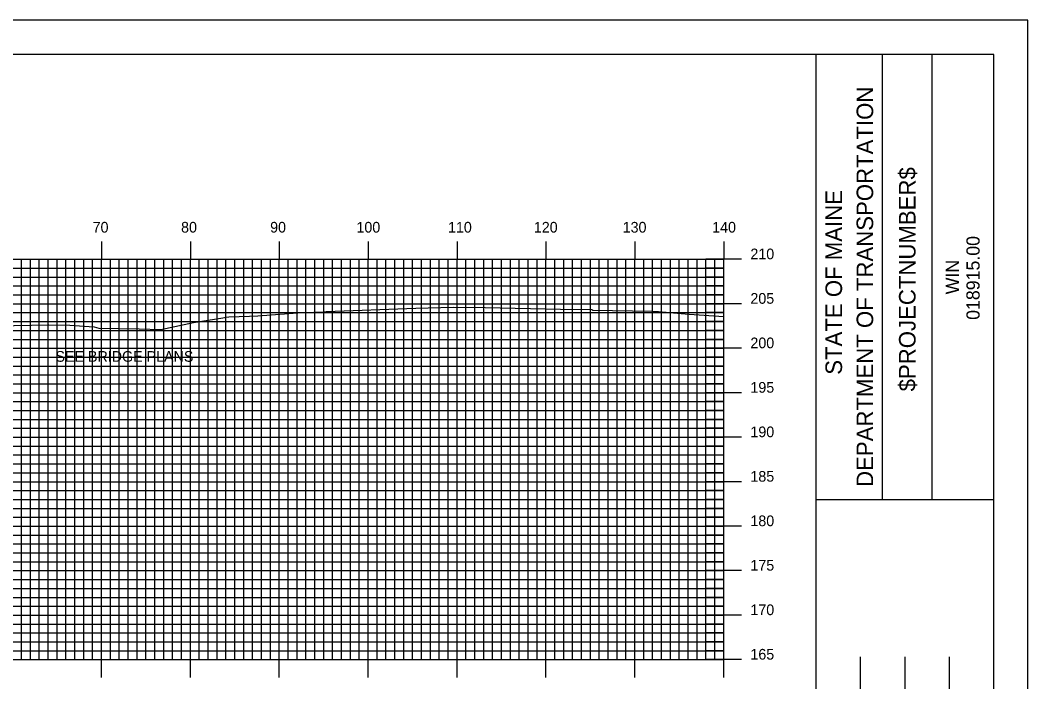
# Model space of a CAD drawing. Extents: x 1795633 to 1795976, y 442591 to 442811.
# Drawn here: x 1795859.7 to 1795973.1, y 442736.2 to 442810.5 of the extents above; entities that cross this region are included whole.
import ezdxf

# ---------------------------------------------------------------- set-up
doc = ezdxf.new("R2010")
doc.units = 0
for name, color, linetype in [('ANNOTATION', 7, 'Continuous'), ('BORDER', 7, 'Continuous'), ('H_V ANNOTATION', 7, 'Continuous'), ('MAJOR', 7, 'Continuous'), ('MINOR', 7, 'Continuous'), ('PLOT BOUNDARY', 7, 'Continuous'), ('S_Roadway_Centerline', 7, 'Continuous')]:
    doc.layers.add(name, color=color, linetype=linetype)

msp = doc.modelspace()

# ---------------------------------------------------------------- linework, layer by layer
at = {"layer": 'BORDER'}
for p, q in [((1795949.28, 442596.67), (1795949.28, 442806.67)), ((1795956.74, 442756.66), (1795956.74, 442806.66)), ((1795962.33, 442756.66), (1795962.33, 442806.66)), ((1795949.28, 442756.65), (1795969.28, 442756.65)), ((1795954.28, 442721.67), (1795954.28, 442738.97)), ((1795959.28, 442721.67), (1795959.28, 442738.97)), ((1795964.28, 442721.67), (1795964.28, 442738.97))]:
    msp.add_line(p, q, dxfattribs=at)
msp.add_lwpolyline([(1795649.28, 442596.67), (1795969.28, 442596.67), (1795969.28, 442806.67), (1795649.28, 442806.67)], close=True, dxfattribs=at)
at = {"layer": 'MAJOR'}
for p, q in [((1795868.88, 442785.67), (1795868.88, 442783.67)), ((1795878.88, 442785.67), (1795878.88, 442783.67)), ((1795888.88, 442785.67), (1795888.88, 442783.67)), ((1795898.88, 442785.67), (1795898.88, 442783.67)), ((1795908.88, 442785.67), (1795908.88, 442783.67)), ((1795918.88, 442785.67), (1795918.88, 442783.67)), ((1795928.88, 442785.67), (1795928.88, 442783.67)), ((1795938.88, 442785.67), (1795938.88, 442783.67)), ((1795658.88, 442783.67), (1795938.88, 442783.67)), ((1795658.88, 442783.67), (1795938.88, 442783.67)), ((1795868.88, 442738.67), (1795868.88, 442783.67)), ((1795878.88, 442738.67), (1795878.88, 442783.67)), ((1795888.88, 442738.67), (1795888.88, 442783.67)), ((1795898.88, 442738.67), (1795898.88, 442783.67)), ((1795908.88, 442738.67), (1795908.88, 442783.67)), ((1795918.88, 442738.67), (1795918.88, 442783.67)), ((1795928.88, 442738.67), (1795928.88, 442783.67)), ((1795940.88, 442783.67), (1795936.88, 442783.67)), ((1795938.88, 442738.67), (1795938.88, 442783.67)), ((1795938.88, 442738.67), (1795938.88, 442783.67)), ((1795658.88, 442778.67), (1795938.88, 442778.67)), ((1795940.88, 442778.67), (1795936.88, 442778.67)), ((1795658.88, 442773.67), (1795938.88, 442773.67)), ((1795940.88, 442773.67), (1795936.88, 442773.67)), ((1795658.88, 442768.67), (1795938.88, 442768.67)), ((1795940.88, 442768.67), (1795936.88, 442768.67)), ((1795658.88, 442763.67), (1795938.88, 442763.67)), ((1795940.88, 442763.67), (1795936.88, 442763.67)), ((1795658.88, 442758.67), (1795938.88, 442758.67)), ((1795940.88, 442758.67), (1795936.88, 442758.67)), ((1795658.88, 442753.67), (1795938.88, 442753.67)), ((1795940.88, 442753.67), (1795936.88, 442753.67)), ((1795658.88, 442748.67), (1795938.88, 442748.67)), ((1795940.88, 442748.67), (1795936.88, 442748.67)), ((1795658.88, 442743.67), (1795938.88, 442743.67)), ((1795940.88, 442743.67), (1795936.88, 442743.67)), ((1795658.88, 442738.67), (1795938.88, 442738.67)), ((1795658.88, 442738.67), (1795938.88, 442738.67)), ((1795868.88, 442736.66), (1795868.88, 442738.67)), ((1795878.88, 442736.66), (1795878.88, 442738.67)), ((1795888.88, 442736.66), (1795888.88, 442738.67)), ((1795898.88, 442736.66), (1795898.88, 442738.67)), ((1795908.88, 442736.66), (1795908.88, 442738.67)), ((1795918.88, 442736.66), (1795918.88, 442738.67)), ((1795928.88, 442736.66), (1795928.88, 442738.67)), ((1795940.88, 442738.67), (1795936.88, 442738.67)), ((1795938.88, 442736.66), (1795938.88, 442738.67))]:
    msp.add_line(p, q, dxfattribs=at)
at = {"layer": 'MINOR'}
for p, q in [((1795859.88, 442738.67), (1795859.88, 442783.67)), ((1795860.88, 442738.67), (1795860.88, 442783.67)), ((1795861.88, 442738.67), (1795861.88, 442783.67)), ((1795862.88, 442738.67), (1795862.88, 442783.67)), ((1795863.88, 442738.67), (1795863.88, 442783.67)), ((1795864.88, 442738.67), (1795864.88, 442783.67)), ((1795865.88, 442738.67), (1795865.88, 442783.67)), ((1795866.88, 442738.67), (1795866.88, 442783.67)), ((1795867.88, 442738.67), (1795867.88, 442783.67)), ((1795869.88, 442738.67), (1795869.88, 442783.67)), ((1795870.88, 442738.67), (1795870.88, 442783.67)), ((1795871.88, 442738.67), (1795871.88, 442783.67)), ((1795872.88, 442738.67), (1795872.88, 442783.67)), ((1795873.88, 442738.67), (1795873.88, 442783.67)), ((1795874.88, 442738.67), (1795874.88, 442783.67)), ((1795875.88, 442738.67), (1795875.88, 442783.67)), ((1795876.88, 442738.67), (1795876.88, 442783.67)), ((1795877.88, 442738.67), (1795877.88, 442783.67)), ((1795879.88, 442738.67), (1795879.88, 442783.67)), ((1795880.88, 442738.67), (1795880.88, 442783.67)), ((1795881.88, 442738.67), (1795881.88, 442783.67)), ((1795882.88, 442738.67), (1795882.88, 442783.67)), ((1795883.88, 442738.67), (1795883.88, 442783.67)), ((1795884.88, 442738.67), (1795884.88, 442783.67)), ((1795885.88, 442738.67), (1795885.88, 442783.67)), ((1795886.88, 442738.67), (1795886.88, 442783.67)), ((1795887.88, 442738.67), (1795887.88, 442783.67)), ((1795889.88, 442738.67), (1795889.88, 442783.67)), ((1795890.88, 442738.67), (1795890.88, 442783.67)), ((1795891.88, 442738.67), (1795891.88, 442783.67)), ((1795892.88, 442738.67), (1795892.88, 442783.67)), ((1795893.88, 442738.67), (1795893.88, 442783.67)), ((1795894.88, 442738.67), (1795894.88, 442783.67)), ((1795895.88, 442738.67), (1795895.88, 442783.67)), ((1795896.88, 442738.67), (1795896.88, 442783.67)), ((1795897.88, 442738.67), (1795897.88, 442783.67)), ((1795899.88, 442738.67), (1795899.88, 442783.67)), ((1795900.88, 442738.67), (1795900.88, 442783.67)), ((1795901.88, 442738.67), (1795901.88, 442783.67)), ((1795902.88, 442738.67), (1795902.88, 442783.67)), ((1795903.88, 442738.67), (1795903.88, 442783.67)), ((1795904.88, 442738.67), (1795904.88, 442783.67)), ((1795905.88, 442738.67), (1795905.88, 442783.67)), ((1795906.88, 442738.67), (1795906.88, 442783.67)), ((1795907.88, 442738.67), (1795907.88, 442783.67)), ((1795909.88, 442738.67), (1795909.88, 442783.67)), ((1795910.88, 442738.67), (1795910.88, 442783.67)), ((1795911.88, 442738.67), (1795911.88, 442783.67)), ((1795912.88, 442738.67), (1795912.88, 442783.67)), ((1795913.88, 442738.67), (1795913.88, 442783.67)), ((1795914.88, 442738.67), (1795914.88, 442783.67)), ((1795915.88, 442738.67), (1795915.88, 442783.67)), ((1795916.88, 442738.67), (1795916.88, 442783.67)), ((1795917.88, 442738.67), (1795917.88, 442783.67)), ((1795919.88, 442738.67), (1795919.88, 442783.67)), ((1795920.88, 442738.67), (1795920.88, 442783.67)), ((1795921.88, 442738.67), (1795921.88, 442783.67)), ((1795922.88, 442738.67), (1795922.88, 442783.67)), ((1795923.88, 442738.67), (1795923.88, 442783.67)), ((1795924.88, 442738.67), (1795924.88, 442783.67)), ((1795925.88, 442738.67), (1795925.88, 442783.67)), ((1795926.88, 442738.67), (1795926.88, 442783.67)), ((1795927.88, 442738.67), (1795927.88, 442783.67)), ((1795929.88, 442738.67), (1795929.88, 442783.67)), ((1795930.88, 442738.67), (1795930.88, 442783.67)), ((1795931.88, 442738.67), (1795931.88, 442783.67)), ((1795932.88, 442738.67), (1795932.88, 442783.67)), ((1795933.88, 442738.67), (1795933.88, 442783.67)), ((1795934.88, 442738.67), (1795934.88, 442783.67)), ((1795935.88, 442738.67), (1795935.88, 442783.67)), ((1795936.88, 442738.67), (1795936.88, 442783.67)), ((1795937.88, 442738.67), (1795937.88, 442783.67)), ((1795658.88, 442782.67), (1795938.88, 442782.67)), ((1795938.88, 442782.67), (1795936.88, 442782.67)), ((1795658.88, 442781.67), (1795938.88, 442781.67)), ((1795658.88, 442780.67), (1795938.88, 442780.67)), ((1795938.88, 442781.67), (1795936.88, 442781.67)), ((1795938.88, 442780.67), (1795936.88, 442780.67)), ((1795658.88, 442779.67), (1795938.88, 442779.67)), ((1795938.88, 442779.67), (1795936.88, 442779.67)), ((1795658.88, 442777.67), (1795938.88, 442777.67)), ((1795938.88, 442777.67), (1795936.88, 442777.67)), ((1795658.88, 442776.67), (1795938.88, 442776.67)), ((1795938.88, 442776.67), (1795936.88, 442776.67)), ((1795658.88, 442775.67), (1795938.88, 442775.67)), ((1795938.88, 442775.67), (1795936.88, 442775.67)), ((1795658.88, 442774.67), (1795938.88, 442774.67)), ((1795938.88, 442774.67), (1795936.88, 442774.67)), ((1795658.88, 442772.67), (1795938.88, 442772.67)), ((1795938.88, 442772.67), (1795936.88, 442772.67)), ((1795658.88, 442771.67), (1795938.88, 442771.67)), ((1795938.88, 442771.67), (1795936.88, 442771.67)), ((1795658.88, 442770.67), (1795938.88, 442770.67)), ((1795938.88, 442770.67), (1795936.88, 442770.67)), ((1795658.88, 442769.67), (1795938.88, 442769.67)), ((1795938.88, 442769.67), (1795936.88, 442769.67)), ((1795658.88, 442767.67), (1795938.88, 442767.67)), ((1795938.88, 442767.67), (1795936.88, 442767.67)), ((1795658.88, 442766.67), (1795938.88, 442766.67)), ((1795938.88, 442766.67), (1795936.88, 442766.67)), ((1795658.88, 442765.67), (1795938.88, 442765.67)), ((1795938.88, 442765.67), (1795936.88, 442765.67)), ((1795658.88, 442764.67), (1795938.88, 442764.67)), ((1795938.88, 442764.67), (1795936.88, 442764.67)), ((1795658.88, 442762.67), (1795938.88, 442762.67)), ((1795938.88, 442762.67), (1795936.88, 442762.67)), ((1795658.88, 442761.67), (1795938.88, 442761.67)), ((1795658.88, 442760.67), (1795938.88, 442760.67)), ((1795938.88, 442760.67), (1795936.88, 442760.67)), ((1795658.88, 442759.67), (1795938.88, 442759.67)), ((1795938.88, 442759.67), (1795936.88, 442759.67)), ((1795658.88, 442757.67), (1795938.88, 442757.67)), ((1795938.88, 442757.67), (1795936.88, 442757.67)), ((1795658.88, 442756.67), (1795938.88, 442756.67)), ((1795658.88, 442755.67), (1795938.88, 442755.67)), ((1795938.88, 442756.67), (1795936.88, 442756.67)), ((1795938.88, 442755.67), (1795936.88, 442755.67)), ((1795658.88, 442754.67), (1795938.88, 442754.67)), ((1795938.88, 442754.67), (1795936.88, 442754.67)), ((1795834.58, 442752.67), (1795938.88, 442752.67)), ((1795938.88, 442752.67), (1795936.88, 442752.67)), ((1795658.88, 442751.67), (1795938.88, 442751.67)), ((1795938.88, 442751.67), (1795936.88, 442751.67)), ((1795658.88, 442750.67), (1795938.88, 442750.67)), ((1795938.88, 442750.67), (1795936.88, 442750.67)), ((1795658.88, 442749.67), (1795938.88, 442749.67)), ((1795938.88, 442749.67), (1795936.88, 442749.67)), ((1795658.88, 442747.67), (1795938.88, 442747.67)), ((1795658.88, 442746.67), (1795938.88, 442746.67)), ((1795938.88, 442747.67), (1795936.88, 442747.67)), ((1795938.88, 442746.67), (1795936.88, 442746.67)), ((1795658.88, 442745.67), (1795938.88, 442745.67)), ((1795938.88, 442745.67), (1795936.88, 442745.67)), ((1795658.88, 442744.67), (1795938.88, 442744.67)), ((1795938.88, 442744.67), (1795936.88, 442744.67)), ((1795658.88, 442742.67), (1795938.88, 442742.67)), ((1795938.88, 442742.67), (1795936.88, 442742.67)), ((1795658.88, 442741.67), (1795938.88, 442741.67)), ((1795938.88, 442741.67), (1795936.88, 442741.67)), ((1795658.88, 442740.67), (1795938.88, 442740.67)), ((1795938.88, 442740.67), (1795936.88, 442740.67)), ((1795658.88, 442739.67), (1795938.88, 442739.67)), ((1795938.88, 442739.67), (1795936.88, 442739.67))]:
    msp.add_line(p, q, dxfattribs=at)
at = {"layer": 'PLOT BOUNDARY'}
msp.add_lwpolyline([(1795633.09, 442590.55), (1795973.09, 442590.55), (1795973.09, 442810.55), (1795633.09, 442810.55)], close=True, dxfattribs=at)
at = {"layer": 'S_Roadway_Centerline'}
msp.add_lwpolyline([(1795857.06, 442776.18), (1795862.97, 442776.3), (1795865.3, 442776.25), (1795868.04, 442776.08), (1795868.56, 442775.91), (1795873.13, 442775.85), (1795875.56, 442775.78), (1795875.57, 442775.77), (1795879.24, 442776.55), (1795882.51, 442777.1), (1795882.9, 442777.18), (1795883.22, 442777.19), (1795885.53, 442777.29), (1795886.45, 442777.33), (1795891.44, 442777.68), (1795891.67, 442777.7), (1795893.86, 442777.78), (1795894.14, 442777.79), (1795904.23, 442778.16), (1795908.44, 442778.29), (1795912.03, 442778.24), (1795920.52, 442778.08), (1795924.05, 442778.03), (1795924.15, 442777.94), (1795930.83, 442777.82), (1795931.53, 442777.79), (1795934.09, 442777.58), (1795934.99, 442777.5), (1795938.88, 442777.25)], dxfattribs=at)

# ---------------------------------------------------------------- texts
at = {"layer": 'ANNOTATION'}
msp.add_text('SEE BRIDGE PLANS', height=1.2, dxfattribs=at).set_placement((1795863.7, 442772.15))
at = {"layer": 'BORDER'}
for s, height, p in [('DEPARTMENT OF TRANSPORTATION', 1.8635, (1795955.69, 442758.08)), ('$PROJECTNUMBER$', 1.8635, (1795960.46, 442768.82)), ('STATE OF MAINE', 1.8635, (1795952.19, 442770.69)), ('018915.00', 1.491, (1795967.67, 442776.86)), ('WIN', 1.491, (1795965.35, 442779.73))]:
    msp.add_text(s, height=height, rotation=90, dxfattribs=at).set_placement(p)
at = {"layer": 'H_V ANNOTATION'}
for s, p in [('70', (1795867.88, 442786.67)), ('80', (1795877.83, 442786.67)), ('90', (1795887.85, 442786.67)), ('100', (1795897.56, 442786.67)), ('110', (1795907.86, 442786.67)), ('120', (1795917.52, 442786.67)), ('130', (1795927.51, 442786.67)), ('140', (1795937.58, 442786.67)), ('210', (1795941.88, 442783.67)), ('205', (1795941.88, 442778.67)), ('200', (1795941.88, 442773.67)), ('195', (1795941.88, 442768.67)), ('190', (1795941.88, 442763.67)), ('185', (1795941.88, 442758.67)), ('180', (1795941.88, 442753.67)), ('175', (1795941.88, 442748.67)), ('170', (1795941.88, 442743.67)), ('165', (1795941.88, 442738.67))]:
    msp.add_text(s, height=1.2, dxfattribs=at).set_placement(p)
at = {"layer": 'S_Roadway_Centerline'}
for s, p in [('C', (1795908.44, 442778.29)), ('C', (1795908.44, 442778.29)), ('L', (1795908.44, 442778.28)), ('L', (1795908.44, 442778.28))]:
    msp.add_text(s, height=0.0146, dxfattribs=at).set_placement(p)

doc.saveas('drawing.dxf')
